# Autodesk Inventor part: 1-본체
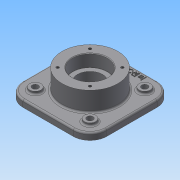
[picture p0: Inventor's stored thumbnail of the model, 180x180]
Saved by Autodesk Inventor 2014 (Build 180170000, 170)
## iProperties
Created: 2015-09
Part Number: 1-본체
Material: Generic
Document SubType Name: Modeling
Designer: study
Density: 1 g/cm^3
Appearance: Default
Author: study
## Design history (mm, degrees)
sketch "스케치1"
  geometry: L1 (-75, 75)-(75, 75); L2 (75, 75)-(75, -75); L3 (75, -75)-(-75, -75); L4 (-75, -75)-(-75, 75); L5 (-75, 75)-(75, -75); L6 (75, 75)-(-75, -75); 1 further point
  constraints: 12 end point, 2 midpoint, 2 parallel, 1 horizontal, 1 perpendicular
  dimensions: "d0" = 150 distance of L1.start L1.end; "d1" = 150 distance of L1.end L2.end
extrude "돌출1" new body sketch "스케치1" distance "d2" = 12; taper "d3" = 0 deg
node "작업 평면1"
sketch "스케치2"
  geometry: C1 r 50 at (0, 0); 1 further point
  constraints: 1 centre point, 1 coincident
  dimensions: "d5" = 100 diameter of C1
extrude "돌출2" join sketch "스케치2" distance "d6" = 70; taper "d7" = 0 deg
hole "구멍1" diameter "d10" = 45; stored, may be unused: countersink angle "d14" = 90 deg, drill point angle "d16" = 118 deg; dims "d8" = 10, "d9" = 10, "d11" = 6, "d12" = 62, "d13" = 22, "d15" = 8
hole "구멍2" diameter "d19" = 45; stored, may be unused: countersink angle "d23" = 90 deg, drill point angle "d25" = 118 deg; dims "d17" = 10, "d18" = 10, "d20" = 6, "d21" = 62, "d22" = 22, "d24" = 8
sketch "스케치3"
  geometry: L1 (49, -49)-(-49, -49); L2 (-49, -49)-(-49, 49); L3 (-49, 49)-(49, 49); L4 (49, 49)-(49, -49); C1 r 50 at (0, 0) reference; C2 r 10 at (-49, 49); C3 r 10 at (49, 49); C4 r 10 at (-49, -49); C5 r 10 at (49, -49); 1 further point
  constraints: 8 end point, 5 coincident, 4 centre point, 3 equal radius, 1 horizontal, 9 other
  dimensions: "d26" = 98 distance of L2.end L3.end; "d27" = 20 diameter of C2
extrude "돌출3" join sketch "스케치3" distance "d28" = 5; taper "d29" = 0 deg
sketch "스케치4"
  geometry: C1 r 10 at (0, 0) reference; C2 r 10 at (98, 0) reference; C3 r 10 at (98, -98) reference; C4 r 10 at (0, -98) reference; 5 further points
  constraints: 4 coincident
hole "구멍3" sketch "스케치4" at (0, 0), (98, 0), (98, -98), (0, -98) diameter "d30" = 11; stored, may be unused: countersink angle "d34" = 90 deg, drill point angle "d36" = 118 deg; dims "d31" = 6, "d32" = 62, "d33" = 22, "d35" = 8
sketch "스케치5"
  geometry: L1 (28.991, -28.991)-(-28.991, -28.991); L2 (-28.991, -28.991)-(-28.991, 28.991); L3 (-28.991, 28.991)-(28.991, 28.991); L4 (28.991, 28.991)-(28.991, -28.991); C1 r 50 at (0, 0) reference; 5 further points
  constraints: 8 end point, 5 coincident, 1 horizontal, 9 other
  dimensions: "d37" = 82 distance of L1.end L3.end
hole "구멍4" sketch "스케치5" at (-28.991, 28.991), (28.991, 28.991), (28.991, -28.991), (-28.991, -28.991) diameter "d38" = 4.917; stored, may be unused: countersink angle "d42" = 90 deg, drill point angle "d44" = 118 deg; dims "d39" = 10, "d40" = 62, "d41" = 22, "d43" = 13
node "작업 평면2"
chamfer "모따기1" distance "d45" = 1; stored, may be unused: second distance "d46" = 2, angle "d47" = 45 deg
fillet "모깎기1" dims "d48" = 0.3, "d49" = 30
fillet "모깎기2" dims "d50" = 3
sketch "스케치6"
  geometry: C1 r 53 at (0, 0) reference; 1 further point
  constraints: 1 vertical alignment, 1 other
  dimensions: "d51" = 65 distance of point (0, 65) C1.centre
feature "엠보싱1" sketch "스케치6" dims "d0" = 150, "d1" = 150, "d52" = 1, "d53" = 0
node "솔리드1"
mirror "대칭1"
other parameters: "d4" = -23
